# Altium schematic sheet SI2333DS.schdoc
size 127 x 101 mm
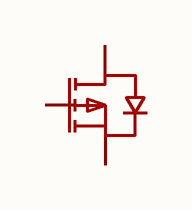
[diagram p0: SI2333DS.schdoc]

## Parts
Q?  si2333ds  [SOT-23-3_L2.9-W1.6-P1.90-LS2.8-BR]  (value not drawn)

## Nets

Not connected (* = marked no-connect by the designer): Q? 1(G) 2(S) 3(D)

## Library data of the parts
Q? = si2333ds: 数量:1个P沟道;漏源电压(Vdss):20V;连续漏极电流(Id):6A;导通电阻(RDS(on)):20mΩ@4.5V;耗散功率(Pd):1.8W;阈值电压(Vgs(th)):1V;; Manufacturer: TECH PUBLIC(台舟); AddInBom: yes; ModelId: 89cb27a44ab2466697082bb9fd73a7d0; ModelName: SOT-23-3L_L2.9-W1.6-H1.1-LS2.8-P0.95; ModelTransform: 114.173,110.236,0,90,0,0,0,0,0; Number: 1个P沟道; Drain to Source Voltage: 20V; Current - Continuous Drain(Id): 6A; Pd - Power Dissipation: 1.8W; Gate Threshold Voltage (Vgs(th)): 1V; Gate Charge(Qg): 19.5nC@4.5V; Input Capacitance(Ciss): 1.73nF; Reverse Transfer Capacitance (Crss@Vds): 210pF; Type: P沟道; Output Capacitance(Coss): 320pF; Vgs: ±12V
